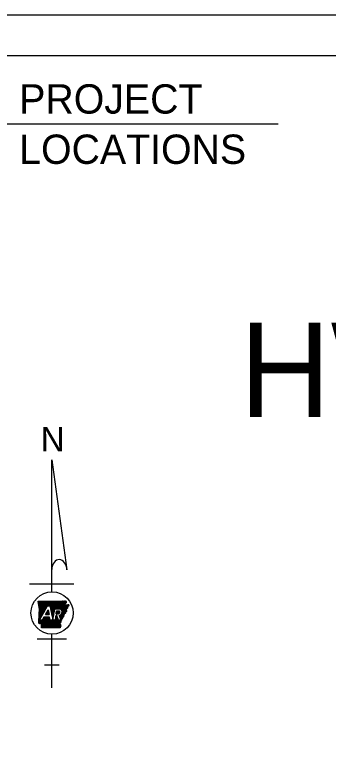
# Model space of a CAD drawing. Extents: x 79818 to 83933, y 50884 to 53307.
# Drawn here: x 81491 to 81790, y 52602 to 53307 of the extents above; entities that cross this region are included whole.
import ezdxf

# ---------------------------------------------------------------- set-up
doc = ezdxf.new("R2010")
doc.units = 0
for name, color, linetype in [('Default', 7, 'Continuous'), ('R_Border', 7, 'Continuous'), ('R_Draft', 7, 'Continuous'), ('R_No Plot', 7, 'Continuous'), ('R_Water Annot', 7, 'Continuous')]:
    doc.layers.add(name, color=color, linetype=linetype)

msp = doc.modelspace()

# ---------------------------------------------------------------- linework, layer by layer
at = {"layer": 'Default'}
msp.add_line((81483.45, 53203.33), (81742.09, 53203.33), dxfattribs=at)
at = {"layer": 'R_Border'}
msp.add_line((80723.6, 53268.52), (83885.4, 53268.52), dxfattribs=at)
at = {"layer": 'R_Draft'}
for p, q in [((81525.99, 52882.61), (81540.55, 52777.43)), ((81525.99, 52756.48), (81525.99, 52882.61)), ((81504.93, 52764.28), (81547.05, 52764.28)), ((81514.2, 52729.43), (81521.98, 52743.17)), ((81519.92, 52734.82), (81522.47, 52739.32)), ((81521.98, 52743.17), (81524.29, 52743.17)), ((81528.98, 52740.3), (81534.38, 52740.3)), ((81530.66, 52738.36), (81533.2, 52738.36)), ((81518.5, 52732.31), (81516.87, 52729.43)), ((81523.96, 52732.31), (81518.5, 52732.31)), ((81519.92, 52734.82), (81523.43, 52734.82)), ((81530.8, 52733.8), (81529.87, 52733.8)), ((81530.15, 52735.43), (81532.47, 52735.43)), ((81532.42, 52729.43), (81530.8, 52733.8)), ((81533.09, 52734.03), (81534.79, 52729.43)), ((81516.87, 52729.43), (81514.2, 52729.43)), ((81529.11, 52729.43), (81524.58, 52729.43)), ((81534.79, 52729.43), (81532.42, 52729.43)), ((81525.99, 52664.95), (81525.99, 52716.14)), ((81511.95, 52711.79), (81540.03, 52711.79)), ((81518.97, 52686.85), (81533.01, 52686.85))]:
    msp.add_line(p, q, dxfattribs=at)
for points in [[(81513.19, 52747.62), (81520.88, 52747.62), (81527.64, 52747.63), (81535.6, 52747.75), (81539.29, 52747.84)], [(81513.19, 52747.62), (81520.88, 52747.62), (81527.63, 52747.63), (81535.6, 52747.75), (81539.29, 52747.84)], [(81514.04, 52735.66), (81514.18, 52739.72), (81513.19, 52747.62)], [(81513.75, 52726.81), (81514.18, 52739.72), (81513.19, 52747.62)], [(81541.7, 52744.31), (81542.37, 52743.61), (81540.71, 52742.25), (81540.89, 52740.87), (81539.47, 52739.93), (81539.95, 52737.81), (81538.86, 52736.81), (81538.76, 52735.72), (81537.42, 52735.24), (81537.22, 52733.19), (81536.26, 52732.16), (81535.79, 52730.62), (81534.4, 52729.34), (81534.5, 52727.09), (81533.56, 52726.02), (81534.42, 52724.09), (81533.82, 52722.17)], [(81538.15, 52744.13), (81541.76, 52744.31)], [(81538.15, 52744.12), (81541.76, 52744.31)], [(81522.47, 52739.32), (81523.43, 52734.82)], [(81524.29, 52743.17), (81527.15, 52729.8), (81528.98, 52740.3)], [(81530.15, 52735.43), (81530.66, 52738.36)], [(81513.75, 52726.81), (81514.04, 52735.66)], [(81524.58, 52729.43), (81523.96, 52732.31)], [(81529.87, 52733.8), (81529.11, 52729.43)], [(81533.82, 52722.17), (81516.39, 52722.2), (81516.38, 52726.05)], [(81533.82, 52722.17), (81516.39, 52722.2), (81516.38, 52726.04)]]:
    msp.add_lwpolyline(points, dxfattribs=at)
for centre, major_axis, ratio, start_param, end_param in [((81533.26, 52777.2), (-0.31, 10.11), 0.719778, 4.712385, 7.768526), ((81531.91, 52737.13), (-1.78, 0), 0.999987, 1.887169, 3.90762), ((81532.37, 52737.45), (-3.49, 0), 0.999987, 1.777838, 4.099264)]:
    msp.add_ellipse(centre, major_axis=major_axis, ratio=ratio, start_param=start_param, end_param=end_param, dxfattribs=at)
msp.add_ellipse((81526.32, 52736.31), major_axis=(20.18, 0), ratio=0.999976, dxfattribs=at)
for points in [[(81539.29, 52747.84), (81539.31, 52747.63), (81539.38, 52747.52), (81539.38, 52747.32), (81539.47, 52747.23), (81539.61, 52747.15), (81539.73, 52747.01), (81539.76, 52746.85), (81539.72, 52746.69), (81539.71, 52746.49), (81539.69, 52746.33), (81539.66, 52746.19), (81539.55, 52746.07), (81539.44, 52745.98), (81539.34, 52745.89), (81539.27, 52745.78), (81539.15, 52745.67), (81539.02, 52745.55), (81538.92, 52745.44), (81538.82, 52745.31), (81538.77, 52745.16), (81538.66, 52745.06), (81538.58, 52744.96), (81538.46, 52744.83), (81538.41, 52744.71), (81538.3, 52744.56), (81538.27, 52744.42), (81538.2, 52744.3), (81538.2, 52744.28)], [(81539.29, 52747.84), (81539.31, 52747.63), (81539.38, 52747.52), (81539.39, 52747.32), (81539.47, 52747.24), (81539.61, 52747.15), (81539.73, 52747.01), (81539.76, 52746.85), (81539.72, 52746.68), (81539.71, 52746.5), (81539.69, 52746.34), (81539.66, 52746.19), (81539.55, 52746.07), (81539.44, 52745.98), (81539.34, 52745.88), (81539.27, 52745.78), (81539.14, 52745.67), (81539.02, 52745.55), (81538.92, 52745.44), (81538.82, 52745.31), (81538.77, 52745.16), (81538.66, 52745.06), (81538.58, 52744.96), (81538.46, 52744.83), (81538.41, 52744.7), (81538.3, 52744.56), (81538.27, 52744.41), (81538.2, 52744.3), (81538.2, 52744.28)], [(81541.7, 52744.31), (81541.76, 52744.31), (81541.92, 52744.14), (81541.99, 52743.99), (81542.09, 52743.92), (81542.21, 52743.87), (81542.3, 52743.76), (81542.36, 52743.64), (81542.33, 52743.54), (81542.2, 52743.53), (81542.05, 52743.51), (81541.91, 52743.51), (81541.79, 52743.41), (81541.9, 52743.29), (81542.04, 52743.17), (81542.08, 52743.04), (81542, 52742.92), (81541.85, 52742.85), (81541.7, 52742.79), (81541.57, 52742.68), (81541.5, 52742.57), (81541.36, 52742.52), (81541.2, 52742.48), (81541.07, 52742.46), (81540.92, 52742.43), (81540.77, 52742.36), (81540.71, 52742.24), (81540.73, 52742.07), (81540.72, 52741.88), (81540.88, 52741.82), (81541.02, 52741.81), (81541.15, 52741.74), (81541.14, 52741.64), (81541.04, 52741.5), (81540.92, 52741.4), (81540.8, 52741.35), (81540.69, 52741.25), (81540.73, 52741.14), (81540.83, 52741.08), (81540.9, 52740.97), (81540.89, 52740.87), (81540.78, 52740.8), (81540.65, 52740.83), (81540.56, 52740.95), (81540.46, 52740.98), (81540.37, 52741.03), (81540.26, 52740.97), (81540.26, 52740.83), (81540.22, 52740.68), (81540.26, 52740.57), (81540.3, 52740.42), (81540.29, 52740.31), (81540.26, 52740.14), (81540.17, 52739.97), (81540.08, 52739.92), (81540.04, 52740.11), (81540.03, 52740.25), (81539.97, 52740.34), (81539.89, 52740.34), (81539.79, 52740.27), (81539.68, 52740.16), (81539.55, 52740.04), (81539.46, 52739.92), (81539.51, 52739.78), (81539.61, 52739.74), (81539.69, 52739.77), (81539.73, 52739.86), (81539.81, 52739.87), (81539.89, 52739.73)], [(81539.89, 52739.73), (81539.91, 52739.59), (81539.83, 52739.45), (81539.8, 52739.3), (81539.81, 52739.15), (81539.66, 52739.07), (81539.53, 52738.97), (81539.61, 52738.86), (81539.75, 52738.75), (81539.89, 52738.68), (81539.98, 52738.59), (81540, 52738.4), (81540.03, 52738.27), (81540.08, 52738.1), (81540.1, 52737.98), (81540.01, 52737.84), (81539.91, 52737.81), (81539.8, 52737.84), (81539.68, 52737.85), (81539.58, 52737.76), (81539.51, 52737.63), (81539.44, 52737.49), (81539.38, 52737.38), (81539.33, 52737.26), (81539.23, 52737.11), (81539.1, 52737.09), (81538.95, 52737.05), (81538.86, 52736.95), (81538.88, 52736.77), (81538.96, 52736.65), (81539.03, 52736.51), (81539.07, 52736.38), (81539.05, 52736.22), (81538.98, 52736.09), (81538.9, 52736.02), (81538.86, 52735.87), (81538.8, 52735.76), (81538.74, 52735.72), (81538.63, 52735.73), (81538.5, 52735.75), (81538.4, 52735.74), (81538.3, 52735.69), (81538.2, 52735.72), (81538.09, 52735.84), (81538.01, 52735.92), (81537.91, 52735.96), (81537.81, 52735.91), (81537.8, 52735.75), (81537.84, 52735.59), (81537.88, 52735.37), (81537.84, 52735.24), (81537.83, 52735.01)], [(81535.19, 52730.51), (81535.18, 52730.51), (81535.09, 52730.4), (81535.14, 52730.23), (81535.33, 52730.16), (81535.41, 52730), (81535.41, 52729.86), (81535.35, 52729.67), (81535.27, 52729.57), (81535.1, 52729.53), (81534.97, 52729.51), (81534.96, 52729.29), (81534.9, 52729.18), (81534.8, 52729.15), (81534.65, 52729.22), (81534.57, 52729.26), (81534.46, 52729.31), (81534.33, 52729.38), (81534.23, 52729.37), (81534.26, 52729.16), (81534.27, 52729.15), (81534.38, 52728.99), (81534.49, 52728.87), (81534.55, 52728.72)], [(81535.19, 52730.51), (81535.18, 52730.51), (81535.09, 52730.4), (81535.14, 52730.23), (81535.33, 52730.16), (81535.41, 52730), (81535.41, 52729.86), (81535.35, 52729.67), (81535.27, 52729.57), (81535.1, 52729.53), (81534.97, 52729.51), (81534.96, 52729.29), (81534.9, 52729.18), (81534.8, 52729.15), (81534.65, 52729.22), (81534.57, 52729.26), (81534.46, 52729.31), (81534.33, 52729.38), (81534.23, 52729.37), (81534.26, 52729.16), (81534.27, 52729.15), (81534.38, 52728.99), (81534.49, 52728.87), (81534.55, 52728.72)], [(81537.83, 52735.01), (81537.66, 52734.89), (81537.59, 52734.76), (81537.16, 52734.8), (81537.17, 52734.65), (81537.02, 52734.57), (81536.89, 52734.47), (81536.97, 52734.36), (81537.11, 52734.25), (81537.25, 52734.17), (81537.34, 52734.09), (81537.36, 52733.89), (81537.39, 52733.77), (81537.44, 52733.6), (81537.46, 52733.48), (81537.37, 52733.34), (81537.27, 52733.31), (81537.17, 52733.35), (81537.04, 52733.35), (81536.94, 52733.26), (81536.87, 52733.13), (81536.8, 52732.99), (81536.75, 52732.88), (81536.69, 52732.75), (81536.59, 52732.61), (81536.47, 52732.59), (81536.31, 52732.55), (81536.22, 52732.45), (81536.24, 52732.27), (81536.32, 52732.15), (81536.39, 52732), (81536.43, 52731.87), (81536.41, 52731.71), (81536.35, 52731.59), (81536.26, 52731.52), (81536.22, 52731.37), (81536.16, 52731.25), (81536.1, 52731.22), (81535.99, 52731.23), (81535.87, 52731.25), (81535.76, 52731.24), (81535.66, 52731.19), (81535.56, 52731.22), (81535.45, 52731.34), (81535.37, 52731.42), (81535.27, 52731.46), (81535.17, 52731.41), (81535.16, 52731.25), (81535.2, 52731.09), (81535.25, 52730.87), (81535.2, 52730.74), (81535.19, 52730.51)], [(81516.38, 52726.05), (81516.4, 52726.04), (81516.31, 52726.1), (81516.18, 52726.16), (81516.05, 52726.17), (81515.87, 52726.19), (81515.72, 52726.21), (81515.57, 52726.31), (81515.41, 52726.2), (81515.23, 52726.13), (81515.12, 52726.21), (81514.99, 52726.15), (81514.89, 52726.19), (81514.73, 52726.07), (81514.57, 52726.11), (81514.45, 52726.08), (81514.31, 52726.08), (81514.28, 52726.25), (81514.14, 52726.27), (81514.02, 52726.34), (81513.95, 52726.5), (81513.89, 52726.63), (81513.75, 52726.81)], [(81516.38, 52726.04), (81516.4, 52726.04), (81516.31, 52726.1), (81516.18, 52726.16), (81516.05, 52726.17), (81515.87, 52726.19), (81515.72, 52726.21), (81515.57, 52726.31), (81515.41, 52726.2), (81515.23, 52726.13), (81515.12, 52726.21), (81514.99, 52726.15), (81514.89, 52726.18), (81514.72, 52726.07), (81514.57, 52726.11), (81514.45, 52726.08), (81514.31, 52726.08), (81514.28, 52726.24), (81514.14, 52726.27), (81514.03, 52726.33), (81513.94, 52726.5), (81513.89, 52726.63), (81513.75, 52726.81)], [(81534.55, 52728.72), (81534.5, 52728.61), (81534.45, 52728.42), (81534.46, 52728.26), (81534.54, 52728.13), (81534.65, 52728.05), (81534.78, 52727.94), (81534.76, 52727.77), (81534.69, 52727.71), (81534.52, 52727.75), (81534.4, 52727.81), (81534.29, 52727.78), (81534.14, 52727.71), (81534.03, 52727.69), (81534.04, 52727.46), (81534.18, 52727.3), (81534.31, 52727.3), (81534.46, 52727.28), (81534.51, 52727.11), (81534.43, 52726.97), (81534.28, 52726.9), (81534.1, 52726.98), (81533.98, 52727.07), (81533.85, 52727.16), (81533.69, 52727.2), (81533.59, 52727.18), (81533.55, 52726.98), (81533.63, 52726.8), (81533.75, 52726.68), (81533.86, 52726.52), (81533.85, 52726.39), (81533.76, 52726.36), (81533.61, 52726.33), (81533.52, 52726.28), (81533.5, 52726.25), (81533.54, 52726.08), (81533.58, 52725.91), (81533.58, 52725.77), (81533.53, 52725.65), (81533.45, 52725.46), (81533.46, 52725.34), (81533.52, 52725.28), (81533.59, 52725.3), (81533.69, 52725.36), (81533.75, 52725.44), (81533.8, 52725.54), (81533.9, 52725.62), (81534.02, 52725.55), (81534.05, 52725.4), (81533.98, 52725.27), (81533.88, 52725.21), (81533.76, 52725.16), (81533.67, 52725.06), (81533.69, 52724.93), (81533.76, 52724.87), (81533.94, 52724.9), (81534.05, 52724.96), (81534.12, 52725.02), (81534.2, 52725.1), (81534.24, 52725.19), (81534.31, 52725.27), (81534.42, 52725.29), (81534.47, 52725.22), (81534.45, 52725.06), (81534.38, 52724.91), (81534.29, 52724.78), (81534.19, 52724.69), (81534.07, 52724.5), (81534.09, 52724.32), (81534.14, 52724.16), (81534.2, 52724.05), (81534.32, 52724.07), (81534.45, 52724.09), (81534.52, 52724.03), (81534.52, 52723.89), (81534.42, 52723.76), (81534.33, 52723.64), (81534.28, 52723.47), (81534.3, 52723.35), (81534.3, 52723.25), (81534.26, 52723.12), (81534.2, 52723.06), (81534.02, 52723.06), (81533.84, 52723.08), (81533.74, 52723.02), (81533.76, 52722.86), (81533.86, 52722.74), (81533.94, 52722.68), (81534.05, 52722.55), (81534.1, 52722.44), (81534.08, 52722.34), (81534.01, 52722.26), (81533.82, 52722.17)], [(81534.55, 52728.72), (81534.5, 52728.61), (81534.45, 52728.42), (81534.46, 52728.26), (81534.54, 52728.13), (81534.65, 52728.05), (81534.78, 52727.94), (81534.76, 52727.77), (81534.69, 52727.71), (81534.52, 52727.75), (81534.4, 52727.81), (81534.29, 52727.78), (81534.14, 52727.71), (81534.03, 52727.69), (81534.04, 52727.46), (81534.18, 52727.3), (81534.31, 52727.3), (81534.46, 52727.28), (81534.51, 52727.11), (81534.43, 52726.97), (81534.28, 52726.9), (81534.1, 52726.98), (81533.98, 52727.07), (81533.85, 52727.16), (81533.69, 52727.2), (81533.59, 52727.18), (81533.55, 52726.98), (81533.63, 52726.8), (81533.75, 52726.68), (81533.86, 52726.52), (81533.85, 52726.39), (81533.76, 52726.36), (81533.61, 52726.33), (81533.52, 52726.28), (81533.5, 52726.25), (81533.54, 52726.08), (81533.58, 52725.91), (81533.58, 52725.77), (81533.53, 52725.65), (81533.45, 52725.46), (81533.46, 52725.34), (81533.52, 52725.28), (81533.59, 52725.3), (81533.69, 52725.36), (81533.75, 52725.44), (81533.8, 52725.54), (81533.9, 52725.62), (81534.02, 52725.55), (81534.05, 52725.4), (81533.98, 52725.27), (81533.88, 52725.21), (81533.76, 52725.16), (81533.67, 52725.06), (81533.69, 52724.93), (81533.76, 52724.87), (81533.94, 52724.9), (81534.05, 52724.96), (81534.12, 52725.02), (81534.2, 52725.1), (81534.24, 52725.19), (81534.31, 52725.27), (81534.42, 52725.29), (81534.47, 52725.22), (81534.45, 52725.06), (81534.38, 52724.91), (81534.29, 52724.78), (81534.19, 52724.69), (81534.07, 52724.5), (81534.09, 52724.32), (81534.14, 52724.16), (81534.2, 52724.05), (81534.32, 52724.07), (81534.45, 52724.09), (81534.52, 52724.03), (81534.52, 52723.89), (81534.42, 52723.76), (81534.33, 52723.64), (81534.28, 52723.47), (81534.3, 52723.35), (81534.3, 52723.25), (81534.26, 52723.12), (81534.2, 52723.06), (81534.02, 52723.06), (81533.84, 52723.08), (81533.74, 52723.02), (81533.76, 52722.86), (81533.86, 52722.74), (81533.94, 52722.68), (81534.05, 52722.55), (81534.1, 52722.44), (81534.08, 52722.34), (81534.01, 52722.26), (81533.82, 52722.17)]]:
    msp.add_spline(points, degree=3, dxfattribs=at)
at = {"layer": 'R_No Plot'}
msp.add_line((80599.59, 53307.47), (83932.93, 53307.47), dxfattribs=at)
msp.add_lwpolyline([(80599.53, 53307.47), (83932.93, 53307.47), (83932.93, 51174.09), (80599.53, 51174.09)], close=True, dxfattribs=at)
at = {"layer": 'R_Water Annot'}
for p, q in [((81513.21, 52747.45), (81513.39, 52747.62)), ((81513.28, 52746.95), (81513.95, 52747.62)), ((81513.34, 52746.45), (81514.5, 52747.62)), ((81513.4, 52745.96), (81515.06, 52747.62)), ((81513.46, 52745.46), (81515.62, 52747.62)), ((81513.52, 52744.97), (81516.17, 52747.62)), ((81513.59, 52744.47), (81516.73, 52747.62)), ((81513.65, 52743.98), (81517.29, 52747.62)), ((81513.71, 52743.48), (81517.85, 52747.62)), ((81513.77, 52742.98), (81518.4, 52747.62)), ((81513.83, 52742.49), (81518.96, 52747.62)), ((81513.89, 52741.99), (81519.52, 52747.62)), ((81513.96, 52741.5), (81520.07, 52747.62)), ((81514.02, 52741), (81520.63, 52747.62)), ((81514.04, 52735.45), (81526.22, 52747.63)), ((81514.06, 52736.02), (81525.66, 52747.63)), ((81514.07, 52736.6), (81525.1, 52747.62)), ((81514.08, 52740.51), (81521.19, 52747.62)), ((81514.09, 52737.18), (81524.54, 52747.62)), ((81514.11, 52737.75), (81523.98, 52747.62)), ((81514.13, 52738.33), (81523.42, 52747.62)), ((81514.14, 52740.01), (81521.75, 52747.62)), ((81514.15, 52738.9), (81522.87, 52747.62)), ((81514.17, 52739.48), (81522.31, 52747.62)), ((81522.31, 52743.17), (81526.78, 52747.63)), ((81522.87, 52743.17), (81527.34, 52747.63)), ((81523.43, 52743.17), (81527.9, 52747.63)), ((81523.99, 52743.17), (81528.46, 52747.64)), ((81524.33, 52742.96), (81529.03, 52747.65)), ((81524.43, 52742.5), (81529.6, 52747.66)), ((81524.53, 52742.04), (81530.16, 52747.67)), ((81524.63, 52741.58), (81530.73, 52747.68)), ((81524.73, 52741.12), (81531.3, 52747.69)), ((81524.83, 52740.66), (81531.86, 52747.7)), ((81524.92, 52740.2), (81532.43, 52747.7)), ((81525.02, 52739.74), (81532.99, 52747.71)), ((81525.12, 52739.28), (81533.56, 52747.72)), ((81525.22, 52738.82), (81534.13, 52747.73)), ((81525.32, 52738.36), (81534.69, 52747.74)), ((81525.42, 52737.9), (81535.26, 52747.75)), ((81525.51, 52737.45), (81535.83, 52747.76)), ((81525.61, 52736.99), (81536.4, 52747.77)), ((81529.49, 52740.3), (81536.97, 52747.79)), ((81530.04, 52740.3), (81537.54, 52747.8)), ((81530.6, 52740.3), (81538.11, 52747.81)), ((81531.16, 52740.3), (81538.68, 52747.83)), ((81531.72, 52740.3), (81539.25, 52747.84)), ((81532.27, 52740.3), (81539.38, 52747.41)), ((81532.83, 52740.3), (81539.65, 52747.12)), ((81533.39, 52740.3), (81539.72, 52746.63)), ((81533.95, 52740.3), (81538.44, 52744.8)), ((81535.27, 52739.4), (81540.1, 52744.22)), ((81535.48, 52739.04), (81540.69, 52744.25)), ((81535.65, 52738.66), (81541.27, 52744.29)), ((81535.77, 52738.23), (81541.8, 52744.26)), ((81513.94, 52732.56), (81518.63, 52737.25)), ((81513.96, 52733.14), (81519.36, 52738.54)), ((81513.98, 52733.72), (81520.08, 52739.82)), ((81514, 52734.29), (81520.81, 52741.11)), ((81514.02, 52734.87), (81521.54, 52742.39)), ((81519.95, 52734.82), (81522.81, 52737.69)), ((81520.51, 52734.82), (81522.91, 52737.23)), ((81520.62, 52736.05), (81522.72, 52738.15)), ((81521.34, 52737.33), (81522.62, 52738.61)), ((81522.07, 52738.62), (81522.52, 52739.07)), ((81525.71, 52736.53), (81528.87, 52739.69)), ((81525.81, 52736.07), (81528.76, 52739.02)), ((81525.91, 52735.61), (81528.64, 52738.34)), ((81526.01, 52735.15), (81528.52, 52737.67)), ((81530.16, 52735.43), (81533.09, 52738.36)), ((81530.27, 52736.1), (81532.53, 52738.36)), ((81530.39, 52736.78), (81531.97, 52738.36)), ((81530.51, 52737.45), (81531.42, 52738.36)), ((81530.62, 52738.13), (81530.86, 52738.36)), ((81530.71, 52735.43), (81533.4, 52738.12)), ((81531.27, 52735.43), (81533.59, 52737.75)), ((81531.83, 52735.43), (81533.69, 52737.29)), ((81533.43, 52733.1), (81539.62, 52739.28)), ((81533.59, 52732.69), (81539.72, 52738.83)), ((81533.74, 52732.29), (81539.82, 52738.38)), ((81533.89, 52731.88), (81539.93, 52737.92)), ((81534.45, 52740.25), (81538.33, 52744.13)), ((81534.76, 52740), (81538.92, 52744.16)), ((81535.03, 52739.71), (81539.51, 52744.19)), ((81535.25, 52735.48), (81539.51, 52739.74)), ((81535.74, 52736.52), (81540.8, 52741.58)), ((81535.85, 52737.75), (81542.06, 52743.96)), ((81535.85, 52737.19), (81540.73, 52742.07)), ((81540.17, 52740.4), (81540.86, 52741.09)), ((81541.82, 52743.15), (81542.32, 52743.66)), ((81513.84, 52729.68), (81514.99, 52730.82)), ((81513.86, 52730.26), (81515.72, 52732.11)), ((81513.88, 52730.83), (81516.45, 52733.39)), ((81513.9, 52731.41), (81517.17, 52734.68)), ((81513.92, 52731.99), (81517.9, 52735.96)), ((81513.97, 52726.45), (81519.82, 52732.31)), ((81514.3, 52726.23), (81520.38, 52732.31)), ((81514.7, 52726.07), (81520.94, 52732.31)), ((81515.36, 52726.18), (81521.5, 52732.31)), ((81515.93, 52726.18), (81522.05, 52732.31)), ((81516.36, 52726.06), (81522.61, 52732.31)), ((81516.38, 52724.97), (81523.73, 52732.31)), ((81516.38, 52725.53), (81523.17, 52732.31)), ((81516.38, 52724.41), (81524.02, 52732.05)), ((81516.39, 52723.86), (81524.12, 52731.59)), ((81516.39, 52723.3), (81524.22, 52731.13)), ((81516.39, 52722.74), (81524.32, 52730.67)), ((81516.4, 52722.2), (81524.41, 52730.21)), ((81517.5, 52730.55), (81519.27, 52732.31)), ((81518.23, 52731.83), (81518.71, 52732.31)), ((81521.06, 52734.82), (81523.01, 52736.77)), ((81521.62, 52734.82), (81523.11, 52736.31)), ((81521.96, 52722.19), (81531.55, 52731.78)), ((81522.18, 52734.82), (81523.21, 52735.85)), ((81522.52, 52722.19), (81531.7, 52731.37)), ((81522.74, 52734.82), (81523.31, 52735.39)), ((81523.08, 52722.19), (81531.85, 52730.96)), ((81523.29, 52734.82), (81523.4, 52734.93)), ((81523.63, 52722.18), (81532, 52730.56)), ((81524.19, 52722.18), (81532.15, 52730.15)), ((81526.1, 52734.69), (81528.4, 52736.99)), ((81526.2, 52734.23), (81528.29, 52736.31)), ((81526.3, 52733.77), (81528.17, 52735.64)), ((81526.4, 52733.31), (81528.05, 52734.96)), ((81526.5, 52732.85), (81527.93, 52734.29)), ((81526.59, 52732.39), (81527.82, 52733.61)), ((81526.69, 52731.93), (81527.7, 52732.94)), ((81526.79, 52731.48), (81527.58, 52732.26)), ((81526.89, 52731.02), (81527.46, 52731.59)), ((81526.99, 52730.56), (81527.34, 52730.91)), ((81527.09, 52730.1), (81527.23, 52730.24)), ((81529.2, 52729.99), (81531.4, 52732.18)), ((81529.32, 52730.66), (81531.25, 52732.59)), ((81529.44, 52731.34), (81531.1, 52733)), ((81529.56, 52732.01), (81530.95, 52733.4)), ((81529.67, 52732.69), (81530.79, 52733.8)), ((81529.79, 52733.36), (81530.23, 52733.8)), ((81532.39, 52735.43), (81533.64, 52736.69)), ((81533.13, 52733.92), (81533.3, 52734.09)), ((81533.28, 52733.51), (81534.35, 52734.57)), ((81534.04, 52731.47), (81537.38, 52734.82)), ((81534.19, 52731.07), (81537.32, 52734.2)), ((81534.34, 52730.66), (81537.26, 52733.58)), ((81534.49, 52730.25), (81536.2, 52731.96)), ((81534.64, 52729.84), (81535.96, 52731.17)), ((81538.02, 52735.46), (81538.8, 52736.24)), ((81513.76, 52726.8), (81516.39, 52729.43)), ((81513.77, 52727.37), (81515.83, 52729.43)), ((81513.79, 52727.95), (81515.27, 52729.43)), ((81513.81, 52728.53), (81514.71, 52729.43)), ((81513.83, 52729.1), (81514.26, 52729.54)), ((81516.95, 52722.2), (81524.51, 52729.75)), ((81517.51, 52722.19), (81524.75, 52729.43)), ((81518.07, 52722.19), (81525.31, 52729.43)), ((81518.62, 52722.19), (81525.86, 52729.43)), ((81519.18, 52722.19), (81526.42, 52729.43)), ((81519.74, 52722.19), (81526.98, 52729.43)), ((81520.29, 52722.19), (81527.54, 52729.43)), ((81520.85, 52722.19), (81528.09, 52729.43)), ((81521.41, 52722.19), (81528.65, 52729.43)), ((81524.75, 52722.18), (81532.3, 52729.74)), ((81525.3, 52722.18), (81532.55, 52729.43)), ((81525.86, 52722.18), (81533.11, 52729.43)), ((81526.42, 52722.18), (81533.67, 52729.43)), ((81526.97, 52722.18), (81534.23, 52729.43)), ((81527.53, 52722.18), (81534.41, 52729.06)), ((81528.09, 52722.18), (81534.44, 52728.53)), ((81528.64, 52722.18), (81534.46, 52728)), ((81529.2, 52722.18), (81534.49, 52727.46)), ((81529.76, 52722.17), (81533.57, 52725.99)), ((81530.31, 52722.17), (81533.74, 52725.61)), ((81530.87, 52722.17), (81533.92, 52725.22)), ((81531.43, 52722.17), (81534.09, 52724.83)), ((81531.98, 52722.17), (81534.26, 52724.45)), ((81532.54, 52722.17), (81534.4, 52724.04)), ((81533.1, 52722.17), (81534.15, 52723.23)), ((81533.65, 52722.17), (81533.9, 52722.42))]:
    msp.add_line(p, q, dxfattribs=at)

# ---------------------------------------------------------------- texts
at = {"layer": 'Default'}
for s, height, p in [('PROJECT', 28, (81494.99, 53213.1)), ('LOCATIONS', 28, (81494.99, 53165.1)), ('HWY.  301 FLOOD DAMAGE', 89.9998, (81705.17, 52923.47))]:
    msp.add_text(s, height=height, dxfattribs=at).set_placement(p)
at = {"layer": 'R_Draft'}
for s, height, p in [('N', 23.47, (81515.53, 52890.54)), ('STS 10-03-17', 0.5833, (81524.39, 52716.3))]:
    msp.add_text(s, height=height, dxfattribs=at).set_placement(p)

doc.saveas('drawing.dxf')
